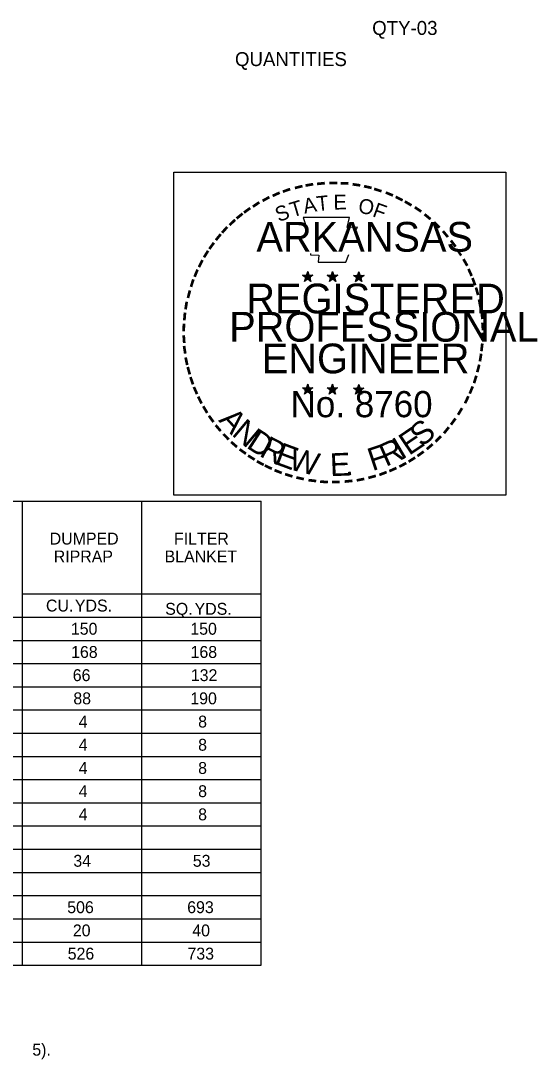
# Model space of a CAD drawing. Extents: x 1226605 to 1228152, y 151309 to 152316.
# Drawn here: x 1227934.5 to 1228151.6, y 151869.1 to 152305.5 of the extents above; entities that cross this region are included whole.
import ezdxf

# ---------------------------------------------------------------- set-up
doc = ezdxf.new("R2010")
doc.units = 0
for name, color, linetype in [('R_Border', 7, 'Continuous'), ('R_Border PE', 7, 'Continuous'), ('R_Border Prem', 7, 'Continuous'), ('R_Dimension', 7, 'Continuous')]:
    doc.layers.add(name, color=color, linetype=linetype)

msp = doc.modelspace()

# ---------------------------------------------------------------- linework, layer by layer
at = {"layer": 'R_Border PE'}
for p, q in [((1228052.94, 152198.54), (1228055.13, 152197.85)), ((1228052.94, 152198.54), (1228054.57, 152198.41)), ((1228052.94, 152198.54), (1228054.57, 152198.29)), ((1228052.94, 152198.54), (1228054.5, 152198.16)), ((1228052.94, 152198.54), (1228054.5, 152197.91)), ((1228052.94, 152198.54), (1228054.44, 152197.79)), ((1228052.94, 152198.54), (1228054.44, 152197.66)), ((1228053.82, 152195.97), (1228055.13, 152197.85)), ((1228053.82, 152195.97), (1228054.5, 152197.72)), ((1228053.82, 152195.97), (1228054.57, 152197.54)), ((1228053.82, 152195.97), (1228054.69, 152197.47)), ((1228053.82, 152195.97), (1228055.13, 152197.35)), ((1228053.82, 152195.97), (1228054.88, 152197.29)), ((1228053.82, 152195.97), (1228055.19, 152197.16)), ((1228055.13, 152200.16), (1228054.82, 152198.6)), ((1228055.13, 152200.16), (1228054.88, 152198.54)), ((1228055.13, 152200.16), (1228055.07, 152198.6)), ((1228055.13, 152197.85), (1228055.13, 152200.16)), ((1228055.13, 152200.16), (1228055.57, 152198.54)), ((1228055.13, 152200.16), (1228055.44, 152198.6)), ((1228055.13, 152200.16), (1228055.32, 152198.6)), ((1228057.32, 152198.54), (1228055.13, 152197.85)), ((1228056.5, 152195.97), (1228055.13, 152197.85)), ((1228056.5, 152195.97), (1228055.13, 152197.35)), ((1228056.5, 152195.97), (1228055.13, 152197.16)), ((1228057.32, 152198.54), (1228055.38, 152198.41)), ((1228056.5, 152195.97), (1228055.38, 152197.29)), ((1228057.32, 152198.54), (1228055.5, 152198.22)), ((1228057.32, 152198.54), (1228055.5, 152198.1)), ((1228056.5, 152195.97), (1228055.57, 152197.54)), ((1228056.5, 152195.97), (1228055.63, 152197.79)), ((1228056.5, 152195.97), (1228055.75, 152197.85)), ((1228057.32, 152198.54), (1228055.94, 152197.97)), ((1228057.32, 152198.54), (1228056.07, 152197.91)), ((1228057.32, 152198.54), (1228056.13, 152197.85)), ((1228063.38, 152198.54), (1228065.57, 152197.85)), ((1228063.38, 152198.54), (1228065, 152198.41)), ((1228063.38, 152198.54), (1228065, 152198.29)), ((1228063.38, 152198.54), (1228064.94, 152198.16)), ((1228063.38, 152198.54), (1228064.88, 152197.91)), ((1228063.38, 152198.54), (1228064.88, 152197.79)), ((1228063.38, 152198.54), (1228064.88, 152197.66)), ((1228064.25, 152195.97), (1228065.57, 152197.85)), ((1228064.25, 152195.97), (1228064.94, 152197.72)), ((1228064.25, 152195.97), (1228065, 152197.54)), ((1228064.25, 152195.97), (1228065.13, 152197.47)), ((1228064.25, 152195.97), (1228065.57, 152197.35)), ((1228064.25, 152195.97), (1228065.32, 152197.29)), ((1228064.25, 152195.97), (1228065.63, 152197.16)), ((1228065.57, 152200.16), (1228065.25, 152198.6)), ((1228065.57, 152200.16), (1228065.32, 152198.54)), ((1228065.57, 152200.16), (1228065.44, 152198.6)), ((1228065.57, 152197.85), (1228065.57, 152200.16)), ((1228065.57, 152200.16), (1228066, 152198.54)), ((1228065.57, 152200.16), (1228065.88, 152198.6)), ((1228065.57, 152200.16), (1228065.69, 152198.6)), ((1228067.75, 152198.54), (1228065.57, 152197.85)), ((1228066.94, 152195.97), (1228065.57, 152197.85)), ((1228066.94, 152195.97), (1228065.57, 152197.35)), ((1228066.94, 152195.97), (1228065.57, 152197.16)), ((1228067.75, 152198.54), (1228065.82, 152198.41)), ((1228066.94, 152195.97), (1228065.82, 152197.29)), ((1228067.75, 152198.54), (1228065.94, 152198.22)), ((1228067.75, 152198.54), (1228065.94, 152198.1)), ((1228066.94, 152195.97), (1228066, 152197.54)), ((1228066.94, 152195.97), (1228066.07, 152197.79)), ((1228066.94, 152195.97), (1228066.19, 152197.85)), ((1228067.75, 152198.54), (1228066.38, 152197.97)), ((1228067.75, 152198.54), (1228066.5, 152197.91)), ((1228067.75, 152198.54), (1228066.57, 152197.85)), ((1228074.44, 152198.47), (1228076.63, 152197.79)), ((1228074.44, 152198.47), (1228076.07, 152198.29)), ((1228074.44, 152198.47), (1228076, 152198.16)), ((1228074.44, 152198.47), (1228076, 152198.1)), ((1228074.44, 152198.47), (1228075.94, 152197.85)), ((1228074.44, 152198.47), (1228075.94, 152197.72)), ((1228074.44, 152198.47), (1228075.94, 152197.6)), ((1228075.25, 152195.91), (1228076.63, 152197.79)), ((1228075.25, 152195.91), (1228076, 152197.66)), ((1228075.25, 152195.91), (1228076.07, 152197.47)), ((1228075.25, 152195.91), (1228076.19, 152197.41)), ((1228075.25, 152195.91), (1228076.63, 152197.29)), ((1228075.25, 152195.91), (1228076.38, 152197.22)), ((1228075.25, 152195.91), (1228076.69, 152197.1)), ((1228076.63, 152200.04), (1228076.25, 152198.54)), ((1228076.63, 152200.04), (1228076.38, 152198.47)), ((1228076.63, 152200.04), (1228076.5, 152198.47)), ((1228076.63, 152197.79), (1228076.63, 152200.04)), ((1228076.63, 152200.04), (1228077.07, 152198.47)), ((1228076.63, 152200.04), (1228076.94, 152198.47)), ((1228076.63, 152200.04), (1228076.75, 152198.54)), ((1228078.82, 152198.47), (1228076.63, 152197.79)), ((1228077.94, 152195.91), (1228076.63, 152197.79)), ((1228077.94, 152195.91), (1228076.63, 152197.29)), ((1228077.94, 152195.91), (1228076.63, 152197.1)), ((1228078.82, 152198.47), (1228076.88, 152198.35)), ((1228077.94, 152195.91), (1228076.88, 152197.22)), ((1228078.82, 152198.47), (1228077, 152198.16)), ((1228078.82, 152198.47), (1228077, 152198.04)), ((1228077.94, 152195.91), (1228077.07, 152197.47)), ((1228077.94, 152195.91), (1228077.13, 152197.72)), ((1228077.94, 152195.91), (1228077.25, 152197.72)), ((1228078.82, 152198.47), (1228077.44, 152197.91)), ((1228078.82, 152198.47), (1228077.5, 152197.85)), ((1228078.82, 152198.47), (1228077.63, 152197.79)), ((1228052.94, 152151.22), (1228055.13, 152150.54)), ((1228052.94, 152151.22), (1228054.57, 152151.04)), ((1228052.94, 152151.22), (1228054.5, 152150.91)), ((1228052.94, 152151.22), (1228054.5, 152150.85)), ((1228052.94, 152151.22), (1228054.44, 152150.6)), ((1228052.94, 152151.22), (1228054.44, 152150.47)), ((1228052.94, 152151.22), (1228054.44, 152150.35)), ((1228053.75, 152148.66), (1228055.13, 152150.54)), ((1228053.75, 152148.66), (1228054.5, 152150.41)), ((1228053.75, 152148.66), (1228054.57, 152150.16)), ((1228053.75, 152148.66), (1228054.69, 152150.1)), ((1228053.75, 152148.66), (1228055.13, 152150.04)), ((1228053.75, 152148.66), (1228054.88, 152149.97)), ((1228053.75, 152148.66), (1228055.13, 152149.85)), ((1228055.13, 152152.79), (1228054.75, 152151.29)), ((1228055.13, 152152.79), (1228054.88, 152151.22)), ((1228055.13, 152152.79), (1228055, 152151.22)), ((1228056.44, 152148.66), (1228055.07, 152149.85)), ((1228055.13, 152150.54), (1228055.13, 152152.79)), ((1228055.13, 152152.79), (1228055.57, 152151.22)), ((1228055.13, 152152.79), (1228055.44, 152151.22)), ((1228055.13, 152152.79), (1228055.25, 152151.22)), ((1228057.32, 152151.22), (1228055.13, 152150.54)), ((1228056.44, 152148.66), (1228055.13, 152150.54)), ((1228056.44, 152148.66), (1228055.13, 152149.97)), ((1228056.44, 152148.66), (1228055.32, 152149.97)), ((1228057.32, 152151.22), (1228055.38, 152151.1)), ((1228057.32, 152151.22), (1228055.5, 152150.91)), ((1228057.32, 152151.22), (1228055.5, 152150.79)), ((1228056.44, 152148.66), (1228055.57, 152150.47)), ((1228056.44, 152148.66), (1228055.57, 152150.22)), ((1228056.44, 152148.66), (1228055.75, 152150.47)), ((1228057.32, 152151.22), (1228055.88, 152150.66)), ((1228057.32, 152151.22), (1228056, 152150.6)), ((1228057.32, 152151.22), (1228056.13, 152150.47)), ((1228063.38, 152151.22), (1228065.57, 152150.54)), ((1228063.38, 152151.22), (1228064.94, 152151.04)), ((1228063.38, 152151.22), (1228064.94, 152150.91)), ((1228063.38, 152151.22), (1228064.94, 152150.85)), ((1228063.38, 152151.22), (1228064.88, 152150.6)), ((1228063.38, 152151.22), (1228064.88, 152150.47)), ((1228063.38, 152151.22), (1228064.88, 152150.35)), ((1228064.19, 152148.66), (1228065.57, 152150.54)), ((1228064.19, 152148.66), (1228064.94, 152150.41)), ((1228064.19, 152148.66), (1228065, 152150.16)), ((1228064.19, 152148.66), (1228065.13, 152150.1)), ((1228064.19, 152148.66), (1228065.57, 152150.04)), ((1228064.19, 152148.66), (1228065.32, 152149.97)), ((1228064.19, 152148.66), (1228065.57, 152149.85)), ((1228065.57, 152152.79), (1228065.19, 152151.29)), ((1228065.57, 152152.79), (1228065.32, 152151.22)), ((1228065.57, 152152.79), (1228065.44, 152151.22)), ((1228066.88, 152148.66), (1228065.5, 152149.85)), ((1228065.57, 152150.54), (1228065.57, 152152.79)), ((1228065.57, 152152.79), (1228065.94, 152151.22)), ((1228065.57, 152152.79), (1228065.88, 152151.22)), ((1228065.57, 152152.79), (1228065.69, 152151.22)), ((1228067.69, 152151.22), (1228065.57, 152150.54)), ((1228066.88, 152148.66), (1228065.57, 152150.54)), ((1228066.88, 152148.66), (1228065.57, 152149.97)), ((1228066.88, 152148.66), (1228065.75, 152149.97)), ((1228067.69, 152151.22), (1228065.82, 152151.1)), ((1228067.69, 152151.22), (1228065.94, 152150.91)), ((1228067.69, 152151.22), (1228065.94, 152150.79)), ((1228066.88, 152148.66), (1228066, 152150.47)), ((1228066.88, 152148.66), (1228066, 152150.22)), ((1228066.88, 152148.66), (1228066.19, 152150.47)), ((1228067.69, 152151.22), (1228066.32, 152150.66)), ((1228067.69, 152151.22), (1228066.44, 152150.6)), ((1228067.69, 152151.22), (1228066.57, 152150.47)), ((1228074.44, 152151.16), (1228076.63, 152150.47)), ((1228074.44, 152151.16), (1228076, 152150.97)), ((1228074.44, 152151.16), (1228076, 152150.85)), ((1228074.44, 152151.16), (1228075.94, 152150.72)), ((1228074.44, 152151.16), (1228075.94, 152150.54)), ((1228074.44, 152151.16), (1228075.88, 152150.35)), ((1228074.44, 152151.16), (1228075.88, 152150.22)), ((1228075.25, 152148.6), (1228076.63, 152150.47)), ((1228075.25, 152148.6), (1228075.94, 152150.35)), ((1228075.25, 152148.6), (1228076, 152150.1)), ((1228075.25, 152148.6), (1228076.19, 152150.04)), ((1228075.25, 152148.6), (1228076.38, 152149.91)), ((1228075.25, 152148.6), (1228076.57, 152149.91)), ((1228075.25, 152148.6), (1228076.63, 152149.79)), ((1228076.63, 152152.72), (1228076.25, 152151.16)), ((1228076.63, 152152.72), (1228076.38, 152151.16)), ((1228076.63, 152152.72), (1228076.5, 152151.16)), ((1228077.94, 152148.6), (1228076.57, 152149.91)), ((1228077.94, 152148.6), (1228076.57, 152149.72)), ((1228076.63, 152150.47), (1228076.63, 152152.72)), ((1228076.63, 152152.72), (1228077, 152151.16)), ((1228076.63, 152152.72), (1228076.94, 152151.16)), ((1228076.63, 152152.72), (1228076.75, 152151.16)), ((1228078.75, 152151.16), (1228076.63, 152150.47)), ((1228077.94, 152148.6), (1228076.63, 152150.47)), ((1228077.94, 152148.6), (1228076.82, 152149.91)), ((1228078.75, 152151.16), (1228076.88, 152151.04)), ((1228078.75, 152151.16), (1228077, 152150.85)), ((1228078.75, 152151.16), (1228077, 152150.72)), ((1228077.94, 152148.6), (1228077, 152150.1)), ((1228077.94, 152148.6), (1228077.07, 152150.41)), ((1228077.94, 152148.6), (1228077.19, 152150.41)), ((1228078.75, 152151.16), (1228077.38, 152150.6)), ((1228078.75, 152151.16), (1228077.5, 152150.47)), ((1228078.75, 152151.16), (1228077.57, 152150.41))]:
    msp.add_line(p, q, dxfattribs=at)
for points in [[(1228053.25, 152222.79), (1228054.88, 152217.6)], [(1228075.19, 152217.04), (1228076.07, 152218.79), (1228071.75, 152218.66), (1228072.69, 152222.79), (1228053.25, 152222.79)], [(1228056.32, 152207.66), (1228056.32, 152207.1), (1228059.82, 152206.97), (1228059.5, 152204.04), (1228071.19, 152204.04), (1228072.44, 152207.35)], [(1228055.13, 152200.16), (1228056.5, 152195.97), (1228052.94, 152198.54), (1228057.32, 152198.54), (1228053.82, 152195.97), (1228055.13, 152200.16)], [(1228065.57, 152200.16), (1228066.94, 152195.97), (1228063.38, 152198.54), (1228067.75, 152198.54), (1228064.25, 152195.97), (1228065.57, 152200.16)], [(1228076.63, 152200.04), (1228077.94, 152195.91), (1228074.44, 152198.47), (1228078.82, 152198.47), (1228075.25, 152195.91), (1228076.63, 152200.04)], [(1228055.13, 152152.79), (1228056.44, 152148.66), (1228052.94, 152151.22), (1228057.32, 152151.22), (1228053.75, 152148.66), (1228055.13, 152152.79)], [(1228065.57, 152152.79), (1228066.88, 152148.66), (1228063.38, 152151.22), (1228067.69, 152151.22), (1228064.19, 152148.66), (1228065.57, 152152.79)], [(1228076.63, 152152.72), (1228077.94, 152148.6), (1228074.44, 152151.16), (1228078.75, 152151.16), (1228075.25, 152148.6), (1228076.63, 152152.72)]]:
    msp.add_lwpolyline(points, dxfattribs=at)
for centre, radius in [((1228055.15, 152197.84), 1.08), ((1228055.15, 152197.84), 0.975), ((1228055.15, 152197.84), 0.904), ((1228055.15, 152197.84), 0.83), ((1228055.15, 152197.84), 0.723), ((1228055.15, 152197.84), 0.672), ((1228055.15, 152197.84), 0.619), ((1228055.15, 152197.84), 0.533), ((1228055.15, 152197.84), 0.467), ((1228055.15, 152197.84), 0.388), ((1228055.15, 152197.84), 0.31), ((1228055.15, 152197.84), 0.231), ((1228055.15, 152197.84), 0.185), ((1228055.15, 152197.84), 0.0901), ((1228065.58, 152197.84), 1.08), ((1228065.58, 152197.84), 0.975), ((1228065.58, 152197.84), 0.904), ((1228065.58, 152197.84), 0.83), ((1228065.58, 152197.84), 0.723), ((1228065.58, 152197.84), 0.672), ((1228065.58, 152197.84), 0.619), ((1228065.58, 152197.84), 0.533), ((1228065.58, 152197.84), 0.467), ((1228065.58, 152197.84), 0.388), ((1228065.58, 152197.84), 0.31), ((1228065.58, 152197.84), 0.231), ((1228065.58, 152197.84), 0.185), ((1228065.58, 152197.84), 0.0901), ((1228076.62, 152197.77), 1.08), ((1228076.62, 152197.77), 0.975), ((1228076.62, 152197.77), 0.904), ((1228076.62, 152197.77), 0.83), ((1228076.62, 152197.77), 0.723), ((1228076.62, 152197.77), 0.672), ((1228076.62, 152197.77), 0.619), ((1228076.62, 152197.77), 0.533), ((1228076.62, 152197.77), 0.467), ((1228076.62, 152197.77), 0.388), ((1228076.62, 152197.77), 0.31), ((1228076.62, 152197.77), 0.231), ((1228076.62, 152197.77), 0.185), ((1228076.62, 152197.77), 0.0901), ((1228055.12, 152150.51), 1.08), ((1228055.12, 152150.51), 0.975), ((1228055.12, 152150.51), 0.904), ((1228055.12, 152150.51), 0.83), ((1228055.12, 152150.51), 0.723), ((1228055.12, 152150.51), 0.672), ((1228055.12, 152150.51), 0.619), ((1228055.12, 152150.51), 0.533), ((1228055.12, 152150.51), 0.467), ((1228055.12, 152150.51), 0.388), ((1228055.12, 152150.51), 0.31), ((1228055.12, 152150.51), 0.231), ((1228055.12, 152150.51), 0.185), ((1228055.12, 152150.51), 0.0901), ((1228065.55, 152150.51), 1.08), ((1228065.55, 152150.51), 0.975), ((1228065.55, 152150.51), 0.904), ((1228065.55, 152150.51), 0.83), ((1228065.55, 152150.51), 0.723), ((1228065.55, 152150.51), 0.672), ((1228065.55, 152150.51), 0.619), ((1228065.55, 152150.51), 0.533), ((1228065.55, 152150.51), 0.467), ((1228065.55, 152150.51), 0.388), ((1228065.55, 152150.51), 0.31), ((1228065.55, 152150.51), 0.231), ((1228065.55, 152150.51), 0.185), ((1228065.55, 152150.51), 0.0901), ((1228076.6, 152150.44), 1.08), ((1228076.6, 152150.44), 0.975), ((1228076.6, 152150.44), 0.904), ((1228076.6, 152150.44), 0.83), ((1228076.6, 152150.44), 0.723), ((1228076.6, 152150.44), 0.672), ((1228076.6, 152150.44), 0.619), ((1228076.6, 152150.44), 0.533), ((1228076.6, 152150.44), 0.467), ((1228076.6, 152150.44), 0.388), ((1228076.6, 152150.44), 0.31), ((1228076.6, 152150.44), 0.231), ((1228076.6, 152150.44), 0.185), ((1228076.6, 152150.44), 0.0901)]:
    msp.add_circle(centre, radius, dxfattribs=at)
at = {"layer": 'R_Border Prem'}
msp.add_lwpolyline([(1227998.91, 152241.83), (1228138.41, 152241.83), (1228138.41, 152106.21), (1227998.91, 152106.21)], close=True, dxfattribs=at)
at = {"layer": 'R_Dimension'}
for p, q in [((1227707.52, 152103.65), (1228035.61, 152103.65)), ((1227935.18, 151908.65), (1227935.18, 152103.65)), ((1227985.39, 151908.65), (1227985.39, 152103.65)), ((1228035.61, 151908.65), (1228035.61, 152103.65)), ((1227935.18, 152064.65), (1228035.61, 152064.65)), ((1227707.52, 152054.9), (1228035.61, 152054.9)), ((1227707.52, 152045.15), (1228035.61, 152045.15)), ((1227707.52, 152035.4), (1228035.61, 152035.4)), ((1227707.52, 152025.65), (1228035.61, 152025.65)), ((1227707.52, 152015.9), (1228035.61, 152015.9)), ((1227707.52, 152006.15), (1228035.61, 152006.15)), ((1227707.52, 151996.4), (1228035.61, 151996.4)), ((1227707.52, 151986.65), (1228035.61, 151986.65)), ((1227707.52, 151976.9), (1228035.61, 151976.9)), ((1227707.52, 151967.15), (1228035.61, 151967.15)), ((1227707.52, 151957.4), (1228035.61, 151957.4)), ((1227707.52, 151947.65), (1228035.61, 151947.65)), ((1227707.52, 151937.9), (1228035.61, 151937.9)), ((1227707.52, 151928.15), (1228035.61, 151928.15)), ((1227707.52, 151918.4), (1228035.61, 151918.4)), ((1227707.52, 151908.65), (1228035.61, 151908.65))]:
    msp.add_line(p, q, dxfattribs=at)

# ---------------------------------------------------------------- texts
at = {"layer": 'R_Border'}
for s, height, p in [('QTY-03', 5.861, (1228082.24, 152299.55)), ('QUANTITIES', 5.862, (1228024.56, 152286.45))]:
    msp.add_text(s, height=height, dxfattribs=at).set_placement(p)
at = {"layer": 'R_Border PE'}
for s, height, rotation, p in [('-', 10, 13.6302, (1228050.07, 152231.35)), ('-', 10, 10.2193, (1228054.32, 152232.35)), ('-', 10, 5.8968, (1228058.88, 152233.04)), ('-', 10, 0.1862, (1228063.69, 152233.47)), ('-', 10, 357.743, (1228068.25, 152233.41)), ('-', 10, 352.1617, (1228072.88, 152233.04)), ('-', 10, 347.2049, (1228077.38, 152232.35)), ('-', 10, 28.7918, (1228037.5, 152226.16)), ('-', 10, 24.3072, (1228041.44, 152228.16)), ('-', 10, 19.1761, (1228045.38, 152229.85)), ('T', 6.25, 6.0228, (1228059.13, 152225.47)), ('E', 6.25, 0.8323, (1228066, 152226.16)), ('-', 10, 342.3362, (1228081.32, 152231.35)), ('-', 10, 337.8551, (1228085.94, 152229.97)), ('-', 10, 334.1211, (1228089.88, 152228.29)), ('-', 10, 36.2317, (1228030.13, 152221.41)), ('-', 10, 34.0636, (1228033.75, 152223.85)), ('S', 6.25, 21.594, (1228042.94, 152220.79)), ('T', 6.25, 16.4036, (1228048.63, 152222.85)), ('A', 6.25, 11.2132, (1228053.82, 152224.41)), ('O', 6.25, 350.4515, (1228076.07, 152224.85)), ('F', 6.25, 340.0707, (1228082, 152223.41)), ('-', 10, 329.6409, (1228093.5, 152226.54)), ('-', 10, 325.8627, (1228097.5, 152224.29)), ('-', 10, 38.9507, (1228027.19, 152219.04)), ('-', 10, 320.5297, (1228101.32, 152221.6)), ('-', 10, 48.423, (1228021.63, 152213.41)), ('-', 10, 42.9622, (1228024.44, 152216.41)), ('-', 10, 315.5786, (1228105.07, 152218.54)), ('-', 10, 50.6142, (1228019.13, 152210.41)), ('-', 10, 309.8797, (1228108.63, 152215.1)), ('-', 10, 54.2325, (1228016.57, 152206.85)), ('-', 10, 306.6522, (1228111.88, 152211.35)), ('-', 10, 58.0706, (1228014.5, 152203.54)), ('-', 8.75, 303.6753, (1228114.94, 152207.79)), ('-', 10, 299.6684, (1228116.94, 152203.97)), ('-', 10, 67.7743, (1228010.94, 152195.91)), ('-', 10, 62.8713, (1228012.57, 152199.72)), ('-', 10, 294.6628, (1228118.94, 152200.16)), ('-', 10, 72.3945, (1228009.57, 152191.97)), ('-', 10, 290.5728, (1228120.57, 152196.6)), ('-', 10, 75.461, (1228008.38, 152187.47)), ('-', 10, 285.1233, (1228122, 152192.97)), ('-', 10, 280.5493, (1228123.25, 152188.29)), ('-', 10, 81.2013, (1228007.5, 152183.04)), ('-', 10, 85.1863, (1228007.07, 152178.72)), ('-', 10, 276.5962, (1228124.32, 152183.54)), ('-', 10, 89.0622, (1228006.88, 152174.35)), ('-', 10, 274.3301, (1228124.69, 152178.97)), ('-', 10, 94.1959, (1228007.13, 152169.79)), ('-', 10, 269.9407, (1228124.88, 152175.04)), ('-', 10, 98.9479, (1228007.57, 152165.66)), ('-', 10, 263.5172, (1228124.75, 152170.91)), ('-', 10, 101.7149, (1228008.38, 152161.04)), ('-', 10, 260.9953, (1228124.32, 152166.79)), ('-', 10, 105.4578, (1228009.44, 152157.35)), ('-', 10, 255.7626, (1228123.63, 152162.54)), ('-', 10, 109.0874, (1228010.75, 152153.41)), ('-', 10, 252.8681, (1228122.5, 152158.04)), ('-', 10, 114.0643, (1228012.38, 152149.66)), ('-', 10, 247.8887, (1228121.13, 152153.85)), ('-', 10, 115.7289, (1228014.25, 152145.79)), ('-', 10, 244.6197, (1228119.44, 152149.91)), ('-', 10, 120.4471, (1228016.5, 152142.16)), ('-', 10, 125.8934, (1228019, 152138.66)), ('A', 9.62, 312.4727, (1228017.38, 152137.47)), ('-', 10, 239.0712, (1228117, 152145.22)), ('-', 10, 130.7181, (1228021.88, 152135.16)), ('N', 9.62, 319.8362, (1228022.81, 152131.54)), ('S', 9.62, 39.723, (1228103.05, 152126.07)), ('-', 10, 233.8452, (1228114.5, 152141.16)), ('-', 10, 134.2238, (1228025.13, 152131.79)), ('D', 9.62, 327.1996, (1228028.96, 152126.35)), ('E', 9.62, 33.8878, (1228097.71, 152122.59)), ('-', 10, 225.7653, (1228108.82, 152134.1)), ('-', 10, 231.2538, (1228111.82, 152137.6)), ('-', 10, 138.9338, (1228028.38, 152128.91)), ('R', 9.62, 333.1738, (1228034.4, 152122.75)), ('E', 9.62, 339.7037, (1228040.75, 152119.48)), ('F', 9.62, 18.6051, (1228082.33, 152116.19)), ('R', 9.62, 24.0235, (1228087.97, 152117.99)), ('I', 9.62, 30.5534, (1228094.5, 152120.84)), ('-', 10, 221.0851, (1228105.57, 152130.91)), ('-', 10, 144.6463, (1228031.88, 152126.35)), ('-', 10, 148.0898, (1228035.38, 152124.04)), ('W', 9.62, 345.5389, (1228046.7, 152117.19)), ('E', 9.62, 2.2804, (1228064.67, 152114.1)), ('-', 10, 212.2491, (1228098.75, 152125.54)), ('-', 10, 215.7363, (1228102.13, 152127.97)), ('-', 10, 151.5704, (1228039, 152121.97)), ('-', 10, 154.6002, (1228042.25, 152120.47)), ('-', 10, 204.2516, (1228091.38, 152121.35)), ('-', 10, 207.3568, (1228095.32, 152123.35)), ('-', 10, 158.5612, (1228046.19, 152118.85)), ('-', 10, 162.7983, (1228050.44, 152117.54)), ('-', 10, 167.5555, (1228054.94, 152116.54)), ('.', 9.62, 8.1156, (1228071.04, 152114.27)), ('-', 10, 195.4743, (1228083.32, 152118.16)), ('-', 10, 200.7184, (1228087.5, 152119.66)), ('-', 10, 173.1155, (1228059.75, 152115.85)), ('-', 10, 176.5183, (1228064.44, 152115.47)), ('-', 10, 181.5918, (1228069.07, 152115.6)), ('-', 10, 185.8167, (1228074.13, 152116.1)), ('-', 10, 191.2858, (1228078.75, 152116.91))]:
    msp.add_text(s, height=height, rotation=rotation, dxfattribs=at).set_placement(p)
for s, height, p in [('ARKANSAS', 12.5, (1228033.57, 152208.47)), ('REGISTERED', 12.5, (1228029.32, 152182.54)), ('PROFESSIONAL', 12.4999, (1228022.13, 152170.66)), ('ENGINEER', 12.5, (1228035.82, 152157.35)), ('No. 8760', 11, (1228047.93, 152138.91))]:
    msp.add_text(s, height=height, dxfattribs=at).set_placement(p)
at = {"layer": 'R_Dimension'}
for s, p in [('DUMPED', (1227946.68, 152085.4)), ('FILTER', (1227998.94, 152085.4)), ('RIPRAP', (1227948.38, 152077.9)), ('BLANKET', (1227994.97, 152077.9)), ('CU.', (1227945.11, 152057.27)), (' YDS.', (1227955.42, 152057.27)), ('SQ.', (1227995.24, 152055.9)), (' YDS.', (1228005.72, 152055.9)), ('150', (1227955.58, 152047.52)), ('150', (1228005.79, 152047.52)), ('168', (1227955.68, 152037.77)), ('168', (1228005.89, 152037.77)), ('66', (1227956.37, 152028.02)), ('132', (1228006.01, 152028.02)), ('88', (1227956.62, 152018.27)), ('190', (1228005.79, 152018.27)), ('4', (1227958.87, 152008.52)), ('8', (1228009.08, 152008.52)), ('4', (1227958.87, 151998.77)), ('8', (1228009.08, 151998.77)), ('4', (1227958.87, 151989.02)), ('8', (1228009.08, 151989.02)), ('4', (1227958.87, 151979.27)), ('8', (1228009.08, 151979.27)), ('4', (1227958.87, 151969.52)), ('8', (1228009.08, 151969.52)), ('34', (1227956.62, 151950.02)), ('53', (1228006.84, 151950.02)), ('506', (1227954.05, 151930.52)), ('693', (1228004.48, 151930.52)), ('20', (1227956.41, 151920.77)), ('40', (1228006.62, 151920.77)), ('526', (1227954.24, 151911.02)), ('733', (1228004.59, 151911.02)), (' 5).', (1227937.51, 151870.65))]:
    msp.add_text(s, height=5, dxfattribs=at).set_placement(p)

doc.saveas('drawing.dxf')
